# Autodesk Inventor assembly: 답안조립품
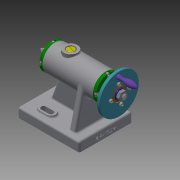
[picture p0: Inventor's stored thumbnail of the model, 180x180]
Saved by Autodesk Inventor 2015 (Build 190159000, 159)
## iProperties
Created: 2022-06
Part Number: 답안조립품
Document SubType Name: Assembly
Designer: 10401
Author: 10401
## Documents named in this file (18)
- C:\Users\10401\Desktop\720606V1016\답안조립품.iam
- C:\Users\10401\Desktop\720606V1016\나사.ipt
- C:\Users\10401\Desktop\720606V1016\나사축.ipt
- C:\Users\10401\Desktop\720606V1016\너트 M8.ipt
- C:\Users\10401\Desktop\720606V1016\돌림판.ipt
- C:\Users\10401\Desktop\720606V1016\멈춤나사 M3.ipt
- C:\Users\10401\Desktop\720606V1016\본체.ipt
- C:\Users\10401\Desktop\720606V1016\볼트 M3.ipt
- C:\Users\10401\Desktop\720606V1016\부시.ipt
- C:\Users\10401\Desktop\720606V1016\센터.ipt
- C:\Users\10401\Desktop\720606V1016\센터홀더.ipt
- C:\Users\10401\Desktop\720606V1016\슬리브.ipt
- C:\Users\10401\Desktop\720606V1016\와셔.ipt
- C:\Users\10401\Desktop\720606V1016\중공축.ipt
- C:\Users\10401\Desktop\720606V1016\커버.ipt
- C:\Users\10401\Desktop\720606V1016\키 4 x 4 x 10.ipt
- C:\Users\10401\Desktop\720606V1016\플랜지.ipt
- C:\Users\10401\Desktop\720606V1016\핸들.ipt
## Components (2 placed, 2 different names)
1. 플랜지:1 — 각도:2
2. 핸들:1
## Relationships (1: Angle 1)
- 각도:2 [Angle]: 플랜지:1
